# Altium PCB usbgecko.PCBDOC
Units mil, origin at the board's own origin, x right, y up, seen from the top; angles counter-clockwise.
Board outline 1185 x 2070 mil, 4 copper layers (Top Layer, Internal Plane 1, Internal Plane 2, Bottom Layer); 14 components, 61 nets, 205 pads, 40 vias.
Unrouted connection lines stored in the file: 1.
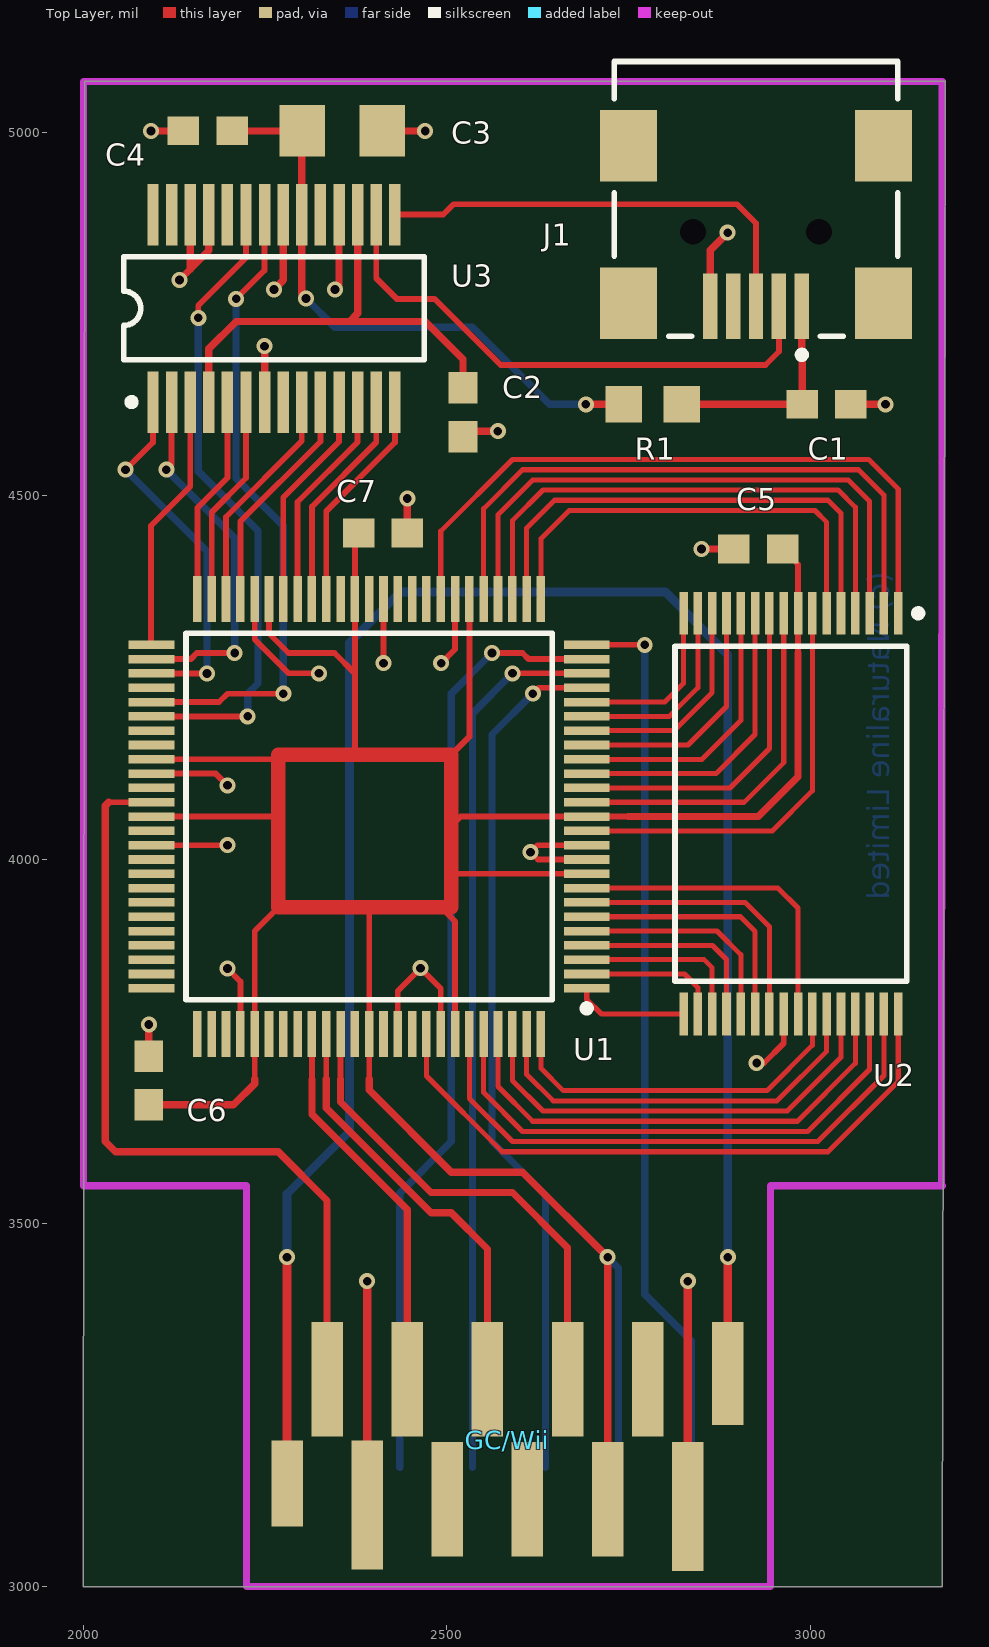
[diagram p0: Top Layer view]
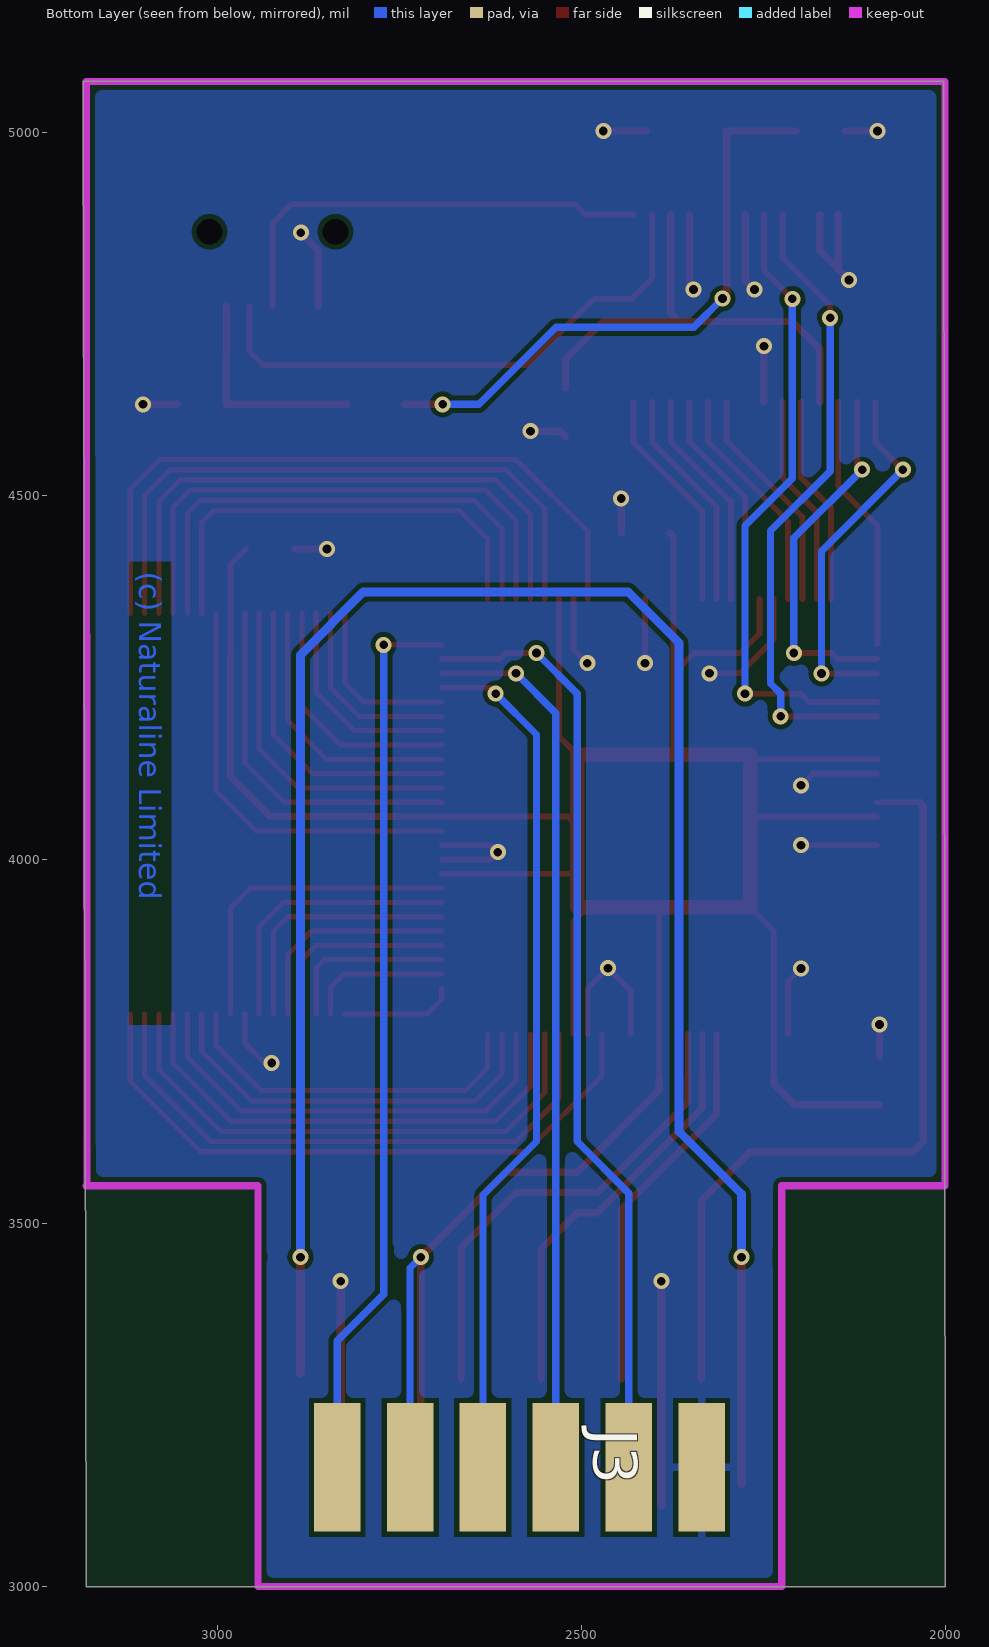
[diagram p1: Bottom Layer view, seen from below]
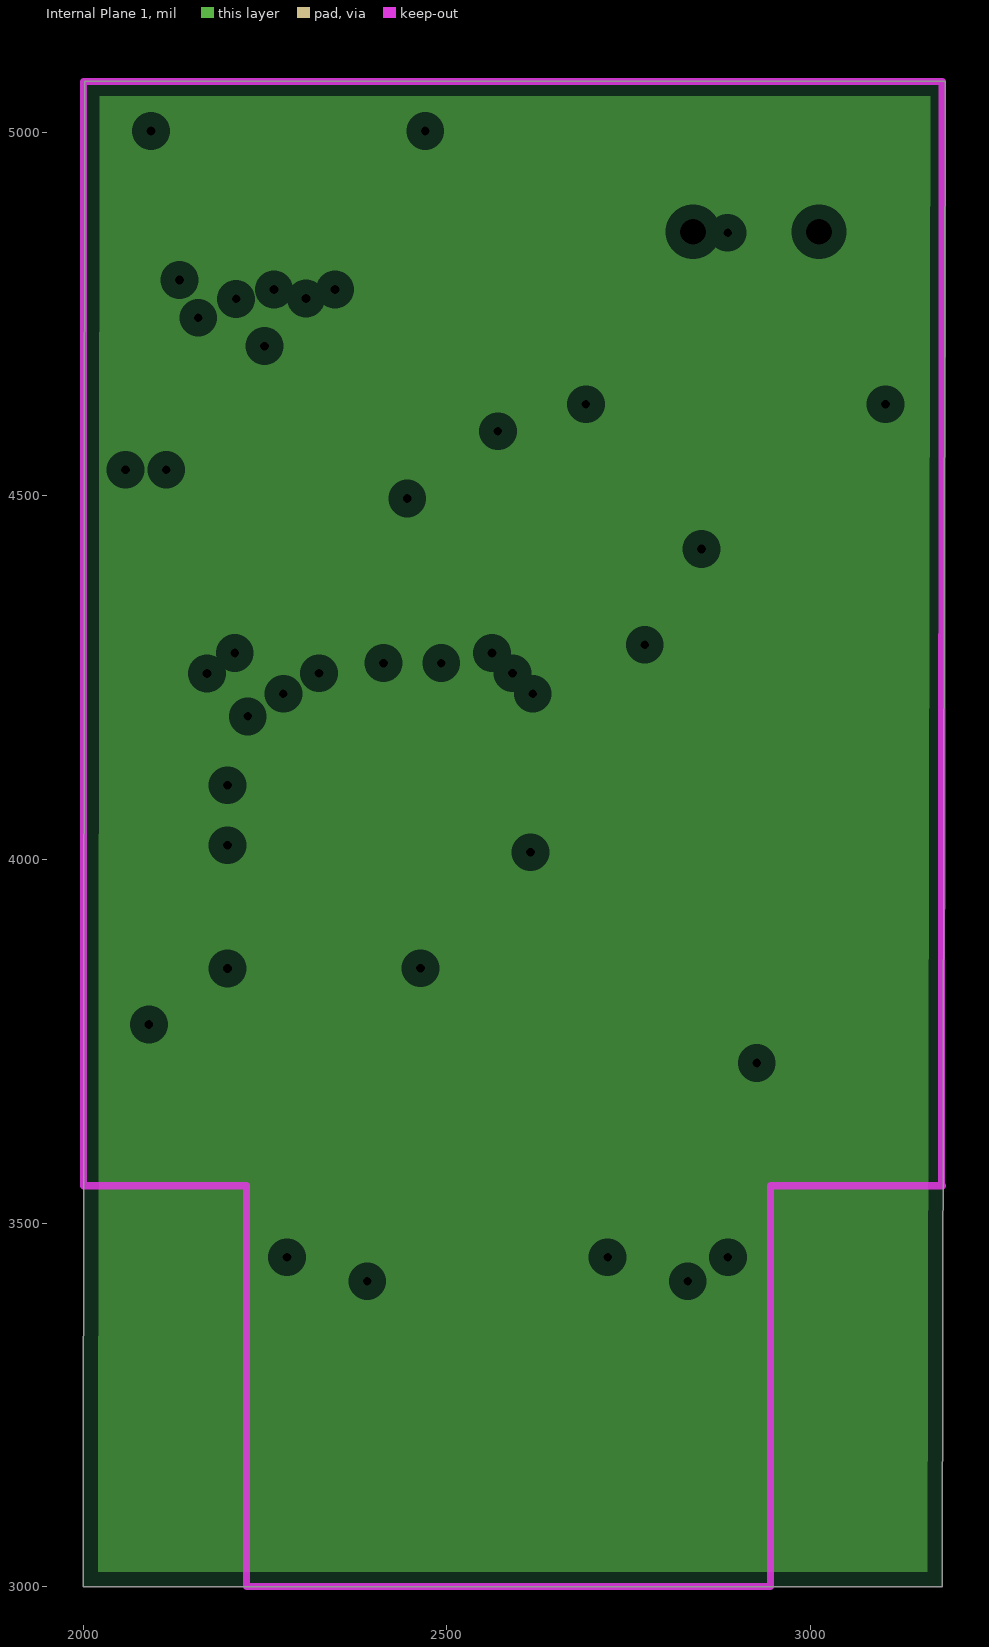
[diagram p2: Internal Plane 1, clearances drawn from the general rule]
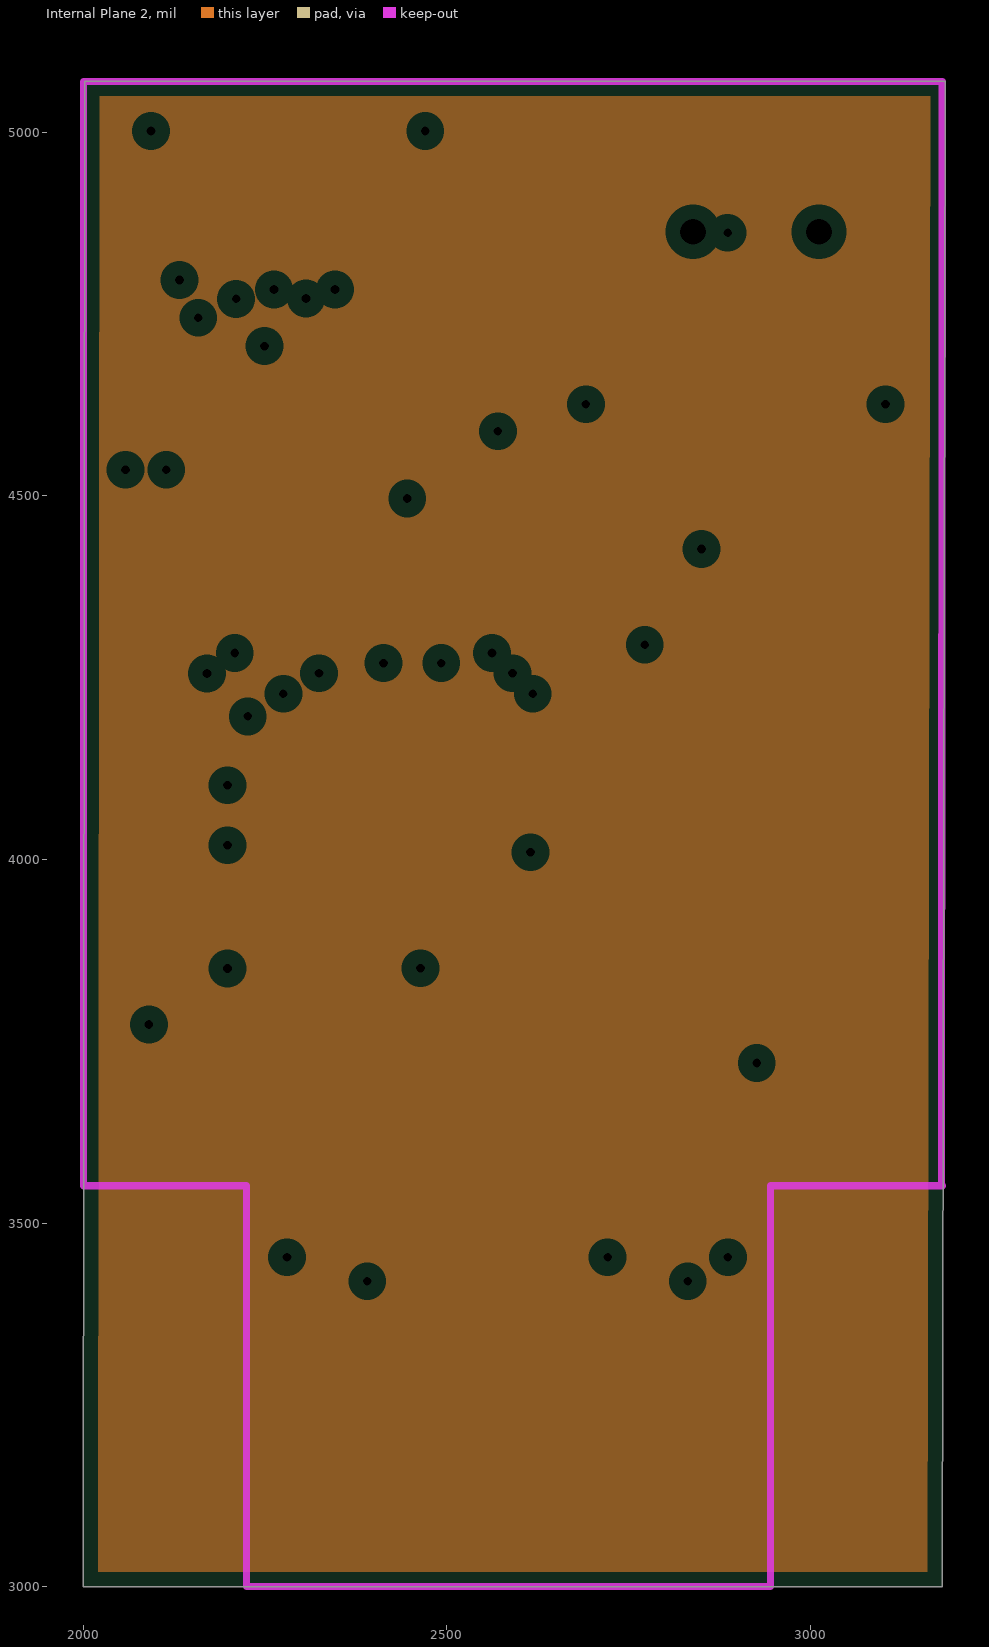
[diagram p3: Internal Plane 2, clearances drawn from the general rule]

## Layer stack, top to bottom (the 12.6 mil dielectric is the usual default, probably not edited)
Top Layer: signal copper 1.4
Dielectric: dielectric 12.6, FR-4, Dk 4.8
Internal Plane 1: plane copper 1.4
Dielectric: dielectric 12.6, FR-4, Dk 4.8
Internal Plane 2: plane copper 1.4
Dielectric: dielectric 12.6, FR-4, Dk 4.8
Bottom Layer: signal copper 1.4

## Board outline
2000,3000 3181.1,3000 3185,5070 2002,5070

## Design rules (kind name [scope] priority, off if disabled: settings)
Clearance [All] p1: gap=7
ComponentClearance [All] p1: gap=10 collisioncheckmode=0
PlaneClearance [All] p1: clearance=20
PlaneConnect [All] p1: planeconnectstyle=Relief reliefexpansion=20 reliefentries=4 reliefconductorwidth=10 reliefairgap=10
PolygonConnect [All] p1: connectstyle=Relief reliefconductorwidth=10 reliefentries=4 polygonreliefangle="90 Angle"
RoomDefinition usbgecko [InComponentClass('usbgecko')] p1 off: confinementstyle=ConfineIn formatcopy=TRUE outline 4747,3108 6747,3108 6747,4108 4747,4108
RoutingLayers [All] p1: top layer=Horizontal bottom layer=Vertical
RoutingVias [All] p1: holewidth=23.62 width=39.37 viastyle="Through Hole" minholewidth=28 minwidth=50 maxholewidth=28 maxwidth=50
SolderMaskExpansion [All] p1: expansion=4
TestPointUsage [All] p1: valid=0 allowmultiple=FALSE
Testpoint [All] p1: side=15 testpointundercomponent=TRUE minsize=40 maxsize=100 preferedsize=60 minholesize=0 maxholesize=40 preferedholesize=32 testpointgrid=1 style=1023 order=-539222988
Width [All] p1: maxlimit=20 minlimit=6 preferedwidth=6
14 further rules are at their usual default settings.

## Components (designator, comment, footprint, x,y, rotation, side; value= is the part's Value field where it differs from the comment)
C1 "0.01uF" 0603 3022,4626 r180 top
C2 "0.1uF" 0603 2522,4615 r270 top
C3 "TANT1206" 1206 2356,5002 r0 top
C4 "0.1uF" 0603 2171,5002 r180 top
C5 "0.1uF" 0603 2928,4427 r180 top
C6 "0.1uF" 0603 2090,3696 r90 top
C7 "0.1uF" 0603 2412,4449 r0 top
GC/Wii "GCMEMPADS" GCMEMPADS 2280,3120 r0 top (schematic designator U4)
J1 "USB-Btype" Mini-USB-SMT 2925,5070 r90 top
J3 "JTAG" JTAG 2836,3164 r180 bottom
R1 "0ohm" RES805 2743,4626 r0 top
U1 "EPM570T100C5" F-QFP14X14-G100/X.3N 2393,4059 r180 top
U2 "39VF040-70N" TSSO8x14-32 2973,4063 r180 top
U3 "FTDI245RL" SSO-G28/X.4 2262,4758 r0 top

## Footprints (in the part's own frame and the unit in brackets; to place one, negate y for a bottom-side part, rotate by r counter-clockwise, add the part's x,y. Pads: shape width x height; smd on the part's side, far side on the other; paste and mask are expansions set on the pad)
0603 [mm]
  rect 1.1x1 smd: 1(-0.85,0) 2(0.85,0)
1206 [mm]
  rect 1.6x1.8 smd: 1(-1.4,0) 2(1.4,0)
F-QFP14X14-G100/X.3N [mm]
  rect 1.6x0.3 smd: 1(-7.6,6) 2(-7.6,5.5) 3(-7.6,5) 4(-7.6,4.5) 5(-7.6,4) 6(-7.6,3.5) 7(-7.6,3) 8(-7.6,2.5) 9(-7.6,2) 10(-7.6,1.5) 11(-7.6,1) 12(-7.6,0.5) 13(-7.6,0) 14(-7.6,-0.5) 15(-7.6,-1) 16(-7.6,-1.5) 17(-7.6,-2) 18(-7.6,-2.5) 19(-7.6,-3) 20(-7.6,-3.5) 21(-7.6,-4) 22(-7.6,-4.5) 23(-7.6,-5) 24(-7.6,-5.5) 25(-7.6,-6) 51(7.6,-6) 52(7.6,-5.5) 53(7.6,-5) 54(7.6,-4.5) 55(7.6,-4) 56(7.6,-3.5) 57(7.6,-3) 58(7.6,-2.5) 59(7.6,-2) 60(7.6,-1.5) 61(7.6,-1) 62(7.6,-0.5) 63(7.6,0) 64(7.6,0.5) 65(7.6,1) 66(7.6,1.5) 67(7.6,2) 68(7.6,2.5) 69(7.6,3) 70(7.6,3.5) 71(7.6,4) 72(7.6,4.5) 73(7.6,5) 74(7.6,5.5) 75(7.6,6)
  rect 0.3x1.6 smd: 26(-6,-7.6) 27(-5.5,-7.6) 28(-5,-7.6) 29(-4.5,-7.6) 30(-4,-7.6) 31(-3.5,-7.6) 32(-3,-7.6) 33(-2.5,-7.6) 34(-2,-7.6) 35(-1.5,-7.6) 36(-1,-7.6) 37(-0.5,-7.6) 38(0,-7.6) 39(0.5,-7.6) 40(1,-7.6) 41(1.5,-7.6) 42(2,-7.6) 43(2.5,-7.6) 44(3,-7.6) 45(3.5,-7.6) 46(4,-7.6) 47(4.5,-7.6) 48(5,-7.6) 49(5.5,-7.6) 50(6,-7.6) 76(6,7.6) 77(5.5,7.6) 78(5,7.6) 79(4.5,7.6) 80(4,7.6) 81(3.5,7.6) 82(3,7.6) 83(2.5,7.6) 84(2,7.6) 85(1.5,7.6) 86(1,7.6) 87(0.5,7.6) 88(0,7.6) 89(-0.5,7.6) 90(-1,7.6) 91(-1.5,7.6) 92(-2,7.6) 93(-2.5,7.6) 94(-3,7.6) 95(-3.5,7.6) 96(-4,7.6) 97(-4.5,7.6) 98(-5,7.6) 99(-5.5,7.6) 100(-6,7.6)
  silkscreen extent -7.73,-6.4 6.4,6.82
GCMEMPADS [mm]
  rect 1.1x3.6 smd: 1(15.4,4.4)
  rect 1.1x4.5 smd: 2(14,-0.25) 10(2.8,-0.2)
  rect 1.1x4 smd: 3(12.6,4.2) 4(11.2,0) 5(9.8,4.2) 6(8.4,0) 7(7,4.2) 8(5.6,0) 9(4.2,4.2) 11(1.4,4.2)
  rect 1.1x3 smd: 12(0,0.55)
JTAG [mil]
  rect 64x177.16 smd: 1(0,0) 2(100.25,0) 3(200.5,0) 4(300.75,0) 5(401,0) 6(501.25,0)
Mini-USB-SMT [mm]
  rect 2.3x0.5 smd: 1(-7.85,-1.6) 2(-7.85,-0.8) 3(-7.85,0) 4(-7.85,0.8) 5(-7.85,1.6)
  rect 2.5x2 smd: 6(-7.75,4.45) 7(-2.25,4.45) 8(-7.75,-4.45) 9(-2.25,-4.45)
  round 0.6 hole 0.9 unplated: MH1(-5.25,2.2) MH2(-5.25,-2.2)
  silkscreen extent -9.67,-4.95 0.7,4.95
RES805 [mil]
  rect 50x50 smd: 1(0,0) 2(80,0)
SSO-G28/X.4 [mm]
  rect 0.4x2.15 smd: 1(-4.225,-3.275) 2(-3.575,-3.275) 3(-2.925,-3.275) 4(-2.275,-3.275) 5(-1.625,-3.275) 6(-0.975,-3.275) 7(-0.325,-3.275) 8(0.325,-3.275) 9(0.975,-3.275) 10(1.625,-3.275) 11(2.275,-3.275) 12(2.925,-3.275) 13(3.575,-3.275) 14(4.225,-3.275) 15(4.225,3.275) 16(3.575,3.275) 17(2.925,3.275) 18(2.275,3.275) 19(1.625,3.275) 20(0.975,3.275) 21(0.325,3.275) 22(-0.325,3.275) 23(-0.975,3.275) 24(-1.625,3.275) 25(-2.275,3.275) 26(-2.925,3.275) 27(-3.575,3.275) 28(-4.225,3.275)
  silkscreen extent -5.25,-3.4 5.25,1.8
TSSO8x14-32 [mm]
  rect 0.3x1.5 smd: 1(-3.75,-7) 2(-3.25,-7) 3(-2.75,-7) 4(-2.25,-7) 5(-1.75,-7) 6(-1.25,-7) 7(-0.75,-7) 8(-0.25,-7) 9(0.25,-7) 10(0.75,-7) 11(1.25,-7) 12(1.75,-7) 13(2.25,-7) 14(2.75,-7) 15(3.25,-7) 16(3.75,-7) 17(3.75,7) 18(3.25,7) 19(2.75,7) 20(2.25,7) 21(1.75,7) 22(1.25,7) 23(0.75,7) 24(0.25,7) 25(-0.25,7) 26(-0.75,7) 27(-1.25,7) 28(-1.75,7) 29(-2.25,7) 30(-2.75,7) 31(-3.25,7) 32(-3.75,7)
  silkscreen extent -4.58,-7.12 4.05,5.85

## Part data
C1 C2 C4 C5 C6 C7: library part CAP603, "Capacitor 603"
C3: "Tant 1206 A106 J106"
GC/Wii: "Gamecube Memory Card Pads"
J1: "USB B Type Right Angle, SMT 5 Pin"
J3: library part JAGAL, "Max II JTAG"
R1: library part RESISTOR805, "Resistor 805 Package"
U1: "MAX II EPM 570 LE CPLD 100 Pin"
U2: "4 Mbit (512Kb x8, Block Erase) Single Supply Flash Memory"
U3: "FTDI 245RL 28 pin SSOP"

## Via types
v1: diameter 22, hole 12, Top Layer to Bottom Layer, 40 vias

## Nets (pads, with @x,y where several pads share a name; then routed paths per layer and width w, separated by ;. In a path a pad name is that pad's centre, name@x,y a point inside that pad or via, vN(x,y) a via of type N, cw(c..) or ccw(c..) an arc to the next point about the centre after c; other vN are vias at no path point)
33VCCIO: C2.1 U3.4 U3.17 | length 651.1
  Top Layer w10: U3.4 2172.43,4702.43 2210,4740 2470,4740 2522,4688 C2.1 ; 2366,4740 2377.16,4751.16 U3.17
A0: U1.4 U2.20 | length 275.4
  Top Layer w7: U1.4 2865.17,3881.83 2884.42,3862.58 U2.20
A1: U1.3 U2.19 | length 240.8
  Top Layer w7: U1.3 2853.69,3862.15 2864.73,3851.1 U2.19
A2: U1.2 U2.18 | length 197
  Top Layer w7: U1.2 2826.54,3842.46 2845.05,3823.95 U2.18
A3: U1.1 U2.17 | length 156.6
  Top Layer w7: U1.1 2692.21,3807.79 2712.59,3787.41 U2.17
A4: U1.21 U2.16 | length 240.1
  Top Layer w7: U1.21 2799.48,4216.48 2825.36,4242.36 U2.16
A5: U1.20 U2.15 | length 271.6
  Top Layer w7: U1.20 2805.8,4196.8 2845.05,4236.05 U2.15
A6: U1.19 U2.14 | length 303.2
  Top Layer w7: U1.19 2812.11,4177.11 2864.73,4229.73 U2.14
A7: U1.18 U2.13 | length 342.3
  Top Layer w7: U1.18 2831.43,4157.43 2884.42,4210.42 U2.13
A8: U1.29 U2.3 | length 813.1
  Top Layer w7: U1.29 2570.17,4474.17 2618,4522 3052,4522 3081.27,4492.73 U2.3
A9: U1.30 U2.2 | length 873.8
  Top Layer w7: U1.30 2550.48,4482.48 2604,4536 3066,4536 3100.95,4501.05 U2.2
A10: U1.95 U2.31 | length 805.4
  Top Layer w7: U1.95 2530.8,3671.2 2590,3612 3010,3612 3100.95,3702.95 U2.31
A11: U1.33 U2.1 | length 950.9
  Top Layer w7: U1.33 2491.43,4451.43 2590,4550 3080,4550 3120.64,4509.36 U2.1
A12: U1.17 U2.12 | length 381.5
  Top Layer w7: U1.17 2850.74,4137.74 2904.1,4191.1 U2.12
A13: U1.28 U2.4 | length 752.4
  Top Layer w7: U1.28 2589.85,4465.85 2632,4508 3038,4508 3061.58,4484.42 U2.4
A14: U1.27 U2.5 | length 690.5
  Top Layer w7: U1.27 2609.54,4455.54 2648,4494 3024,4494 3041.9,4476.1 U2.5
A15: U1.16 U2.11 | length 420.6
  Top Layer w7: U1.16 2870.06,4118.06 2923.79,4171.79 U2.11
A16: U1.15 U2.10 | length 459.8
  Top Layer w7: U1.15 2889.37,4098.37 2943.47,4152.47 U2.10
A17: U1.26 U2.6 | length 624
  Top Layer w7: U1.26 2629.22,4441.22 2668,4480 3006,4480 3022.21,4463.79 U2.6
A18: U1.14 U2.9 | length 498.9
  Top Layer w7: U1.14 2908.69,4078.69 2963.16,4133.16 U2.9
CE#: U1.96 U2.30 | length 744.7
  Top Layer w7: U1.96 2550.48,3679.52 2604,3626 2996,3626 3081.27,3711.27 U2.30
D0: U1.5 U2.21 | length 306.9
  Top Layer w7: U1.5 2871.48,3901.52 2904.1,3868.9 U2.21
D1: U1.6 U2.22 | length 353.7
  Top Layer w7: U1.6 2903.8,3921.21 2923.79,3901.21 U2.22
D2: U1.7 U2.23 | length 385.2
  Top Layer w7: U1.7 2910.11,3940.89 2943.47,3907.53 U2.23
D3: U1.8 U2.25 | length 447.7
  Top Layer w7: U1.8 2955.43,3960.58 2982.84,3933.16 U2.25
D4: U1.100 U2.26 | length 501.8
  Top Layer w7: U1.100 2629.22,3712.78 2660,3682 2940,3682 3002.53,3744.53 U2.26
D5: U1.99 U2.27 | length 562.6
  Top Layer w7: U1.99 2609.54,3704.46 2646,3668 2954,3668 3022.21,3736.21 U2.27
D6: U1.98 U2.28 | length 623.3
  Top Layer w7: U1.98 2589.85,3696.15 2632,3654 2968,3654 3041.9,3727.9 U2.28
D7: U1.97 U2.29 | length 684
  Top Layer w7: U1.97 2570.17,3687.83 2618,3640 2982,3640 3061.58,3719.58 U2.29
EXT: GC/Wii.1 GC/Wii.12 | length 2765.5
  Top Layer w12: GC/Wii.12 v1(2280,3453.06) ; GC/Wii.1 v1(2886.3,3453.06)
  Bottom Layer w12: v1(2280,3453.06) 2280,3540 2366,3626 2366,4298 2436,4368 2800,4368 2886.3,4281.7 v1(2886.3,3453.06)
GCCLK: GC/Wii.11 U1.62 | length 1112
  Top Layer w8: 2034.68,4078.68 U1.62
  Top Layer w10: 2034.68,4078.68 2030,4074 2030,3612 2044,3598 2268,3598 2335.12,3530.88 GC/Wii.11
GCCS: GC/Wii.9 U1.84 | length 528.7
  Top Layer w8: 2314.26,3698 U1.84
  Top Layer w10: 2314.26,3698 2314.26,3649.74 2445.35,3518.65 GC/Wii.9
GCDI: GC/Wii.7 U1.85 | length 582.6
  Top Layer w8: 2333.94,3698 U1.85
  Top Layer w10: 2333.94,3698 2333.94,3658.06 2478,3514 2506,3514 2555.59,3464.41 GC/Wii.7
GCDO: GC/Wii.5 U1.86 | length 669.4
  Top Layer w8: 2353.63,3698 U1.86
  Top Layer w10: 2353.63,3698 2353.63,3666.37 2478,3542 2590,3542 2665.83,3466.17 GC/Wii.5
GND: C1.1 C2.2 C3.2 C4.2 C5.2 C6.2 C7.2 GC/Wii.2 GC/Wii.10 J1.5 J3.6 U1.10 U1.11 U1.32 U1.37 U1.46 U1.60 U1.65 U1.79 U1.90 U1.93 U2.24 U3.7 U3.18 U3.21 U3.25 U3.26 | length 2655.8
  Top Layer w8: U1.65 v1(2198,4019.63) ; U1.60 2181.94,4118.06 v1(2198,4102) ; v1(2198,3850) 2215.84,3832.16 U1.79 ; U1.46 2235.52,4302.48 2282,4256 v1(2324,4256) ; v1(2412.69,4270) U1.37 ; U1.90 2432.37,3819.22 v1(2463.57,3850.43) 2491.43,3822.57 U1.93 ; v1(2492,4270) 2511.11,4289.11 U1.32 ; U1.10 2625.06,3999.94 v1(2615,4010) 2624.63,4019.63 U1.11 ; v1(2926,3720) 2936,3720 2963.16,3747.16 U2.24
  Top Layer w10: C6.2 v1(2090,3773) ; v1(2093,5002) C4.2 ; v1(2132,4797) 2172.43,4837.43 U3.25 ; 2146.84,4811.84 U3.26 ; U3.7 v1@2249.2,4705.8 ; v1(2262,4784) 2274.8,4796.8 U3.21 ; v1(2346,4784) 2351.57,4789.57 U3.18 ; C3.2 v1(2470,5002) ; C7.2 v1(2445.47,4496.53) ; C2.2 2529.46,4589 v1(2570,4589) ; v1(2850,4427) C5.2 ; J1.5 2862.01,4838.01 v1(2886,4862) ; C1.1 v1(3103,4626)
  Top Layer w12: GC/Wii.10 v1(2390.24,3420) ; GC/Wii.2 v1(2831.18,3420)
  other v1: 2249,4706
Net_1: 
Net_1: 
Net_6: 
OE#: U1.92 U2.32 | length 882.4
  Top Layer w7: U1.92 2471.74,3702.26 2576,3598 3024,3598 3120.64,3694.64 U2.32
TCK: J3.5 U1.24 | length 1306.3
  Top Layer w8: v1(2562,4284) 2604,4284 2612.46,4275.54 U1.24
  Bottom Layer w10: J3.5 2435,3541 2506,3612 2506,4228 v1(2562,4284)
TDI: J3.4 U1.23 | length 1216.9
  Top Layer w8: v1(2590,4256) U1.23
  Bottom Layer w10: J3.4 2535.25,4201.25 v1(2590,4256)
TDO: J3.1 U1.25 | length 1237.5
  Top Layer w8: U1.25 v1(2772,4295.22)
  Bottom Layer w10: v1(2772,4295.22) 2772,3402 2836,3338 J3.1
TMS: J3.3 U1.22 | length 1195.2
  Top Layer w8: v1(2618,4228) 2626.17,4236.17 U1.22
  Bottom Layer w10: v1(2618,4228) 2562,4172 2562,3612 2635.5,3538.5 J3.3
USBD0: U1.53 U3.1 | length 511.3
  Top Layer w8: v1(2058,4536) 2095.66,4573.66 U3.1 ; U1.53 v1(2170,4255.85)
  Bottom Layer w10: v1(2058,4536) 2170,4424 v1@2170,4256
USBD1: U1.50 U3.5 | length 287.9
  Top Layer w8: U1.50 2156.78,4483.78 2198.02,4525.02 U3.5
USBD2: U1.51 U3.3 | length 355.4
  Top Layer w8: U1.51@2093,4296.01 2093,4459 2146.84,4512.84 U3.3
USBD3: U1.44 U3.11 | length 302.6
  Top Layer w8: U1.44 2274.89,4497.89 2351.57,4574.57 U3.11
USBD4: U1.52 U3.2 | length 504.7
  Top Layer w8: U1.52 2147.54,4275.54 2156,4284 v1(2208,4284) ; v1(2114,4536) 2121.25,4543.25 U3.2
  Bottom Layer w10: v1(2114,4536) 2208,4442 v1(2208,4284)
USBD5: U1.48 U3.9 | length 314
  Top Layer w8: U1.48 2196.15,4471.15 2300.39,4575.39 U3.9
USBD6: U1.47 U3.10 | length 316.5
  Top Layer w8: U1.47 2215.83,4464.83 2325.98,4574.98 U3.10
USBD7: U1.49 U3.6 | length 290.4
  Top Layer w8: U1.49 2176.46,4477.46 2223.61,4524.61 U3.6
USBDM: J1.2 U3.16 | length 760.9
  Top Layer w8: U3.16 2402.75,4799.25 2431,4771 2483,4771 2574,4680 2938,4680 2956.5,4698.5 J1.2
USBDP: J1.3 U3.15 | length 627.3
  Top Layer w8: U3.15 2494.94,4886.94 2509,4901 2899,4901 2925,4875 J1.3
USBPWREN: U1.43 U3.12 | length 305.1
  Top Layer w8: U1.43 2294.57,4491.57 2377.16,4574.16 U3.12
USBRD#: U1.42 U3.13 | length 307.5
  Top Layer w8: U1.42 2314.26,4485.26 2402.75,4573.75 U3.13
USBRXF#: U1.56 U3.23 | length 889.3
  Top Layer w8: U1.56 v1(2226,4196.8) ; v1(2158,4745) 2158,4762 2223.61,4827.61 U3.23
  Bottom Layer w10: v1(2158,4745) 2158,4534 2240,4452 2240,4242 2226,4228 v1(2226,4196.8)
USBTXE#: U1.55 U3.22 | length 888.1
  Top Layer w8: U1.55 2186.48,4216.48 2198,4228 v1(2275,4228) ; v1(2210,4771) 2249.2,4810.2 U3.22
  Bottom Layer w10: v1(2210,4771) 2210,4524 2275,4459 v1(2275,4228)
USBWR: U1.41 U3.14 | length 310
  Top Layer w8: U1.41 2333.94,4478.94 2428.34,4573.34 U3.14
VCC5: C1.2 C3.1 C4.1 J1.1 R1.1 R1.2 U3.20 | length 1126.4
  Top Layer w10: C4.1 C3.1 ; C3.1@2300.39,5001.5 U3.20 2300.39,4777.23 v1(2306,4771.61) ; v1(2691,4626) R1.1 ; R1.2 C1.2 J1.1
  Bottom Layer w10: v1(2306,4771.61) 2345.61,4732 2535,4732 2641,4626 v1(2691,4626)
VCC33: C5.1 C6.1 C7.1 GC/Wii.4 J3.2 U1.9 U1.13 U1.31 U1.39 U1.45 U1.59 U1.63 U1.80 U1.88 U1.94 U2.8 | length 4882.9
  Top Layer w8: U1.63 2267,4059 ; U1.59 2260.26,4137.74 2268,4130 ; 2235.52,3698 U1.80 2235.52,3901.52 2268,3934 ; U1.45 2255.2,4310.8 2282,4284 2345.32,4284 2373.32,4256 ; 2366,4144 2373.32,4151.32 U1.39 C7.1@2373.32,4443.78 ; 2393,3698 U1.88 2393,3933 ; 2492,3934 2511.11,3914.89 U1.94 ; 2506,3976 2510.26,3980.26 U1.9 ; 2506,4046 2519,4059 U1.13 2749,4059 ; 2506,4144 2530.8,4168.8 U1.31 ; C5.1 2982.84,4405.62 U2.8 2982.84,4284.16
  Top Layer w10: C6.1 2206.54,3662.54 2235.52,3691.52 2235.52,3698 ; C7.1@2373.32,4443.78 C7.1 ; 2393,3698 2393,3683 2506,3570 2604,3570 v1(2720.94,3453.06) GC/Wii.4 ; 2393,3933 2394,3934 ; 2749,4059 2928,4059 2982.84,4113.84 2982.84,4284.16
  Top Layer w20: 2268,3934 2506,3934 2506,4144 2268,4144 2268,3934
  Bottom Layer w10: v1(2720.94,3453.06) 2735.75,3438.25 J3.2
WE#: U1.12 U2.7 | length 577.2
  Top Layer w7: U1.12 2947.32,4039.32 3002.53,4094.53 U2.7
pads on no net: GC/Wii.3 GC/Wii.6 GC/Wii.8 J1.4 J1.6 J1.7 J1.8 J1.9 J1.MH1 J1.MH2 U1.34 U1.35 U1.36 U1.38 U1.40 U1.54 U1.57 U1.58 U1.61 U1.64 U1.66 U1.67 U1.68 U1.69 U1.70 U1.71 U1.72 U1.73 U1.74 U1.75 U1.76 U1.77 U1.78 U1.81 U1.82 U1.83 U1.87 U1.89 U1.91 U3.8 U3.19 U3.24 U3.27 U3.28

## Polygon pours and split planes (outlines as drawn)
GND on Bottom Layer (hatched 90Degree grid 1 track 20, remove dead copper): 2002,5068 3178,5068 3178,2996 2002,2996
no net on Internal Plane 1 (split plane): 2020.03,3020.01 2022,5049.98 3164.95,5049.98 3161.12,3020.01
no net on Internal Plane 2 (split plane): 2020.03,3020.01 2022,5049.98 3164.95,5049.98 3161.12,3020.01

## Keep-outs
Keep-Out Layer:
  lines w10: 3180,3551.18 3181.1,5070 2000,5070 2000,3551.18 2224.41,3551.18 2224.41,3000 2944.88,3000 2944.88,3551.18 3181.1,3551.18

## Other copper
Bottom Layer:
  text "(c) Naturaline Limited" at 3108,4396 h30 r90

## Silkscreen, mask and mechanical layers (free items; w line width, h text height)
Drill Drawing:
  text ".LEGEND" at 3490,3230 h60
  text "Drill Drawing." at 3381.1,3100 h60

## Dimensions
2224.41,3000 to 2944.88,3000 on Mechanical 1
2000,3551.18 to 2000,5070 on Mechanical 1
